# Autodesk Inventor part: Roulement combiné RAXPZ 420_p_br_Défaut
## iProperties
Shininess: 64.0
Length Units: 11269
Angle Units: 11279
Time Units: 11290
Mass Units: 11283
Length Display Precision: 3
Angle Display Precision: 2
Compacted: True
Part Number: Roulement combiné RAXPZ 420_p_br_Défaut
Document SubType Name: Modeling
Created: 2006-01
Material: Par défaut
Designer: riri
Density: 0.0
Volumn: 0.0
Area: 0.0
PropertySet Name: Model Information
Control State: 0
Master: False
Checked Out: False
Author: riri
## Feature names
1. Base1
